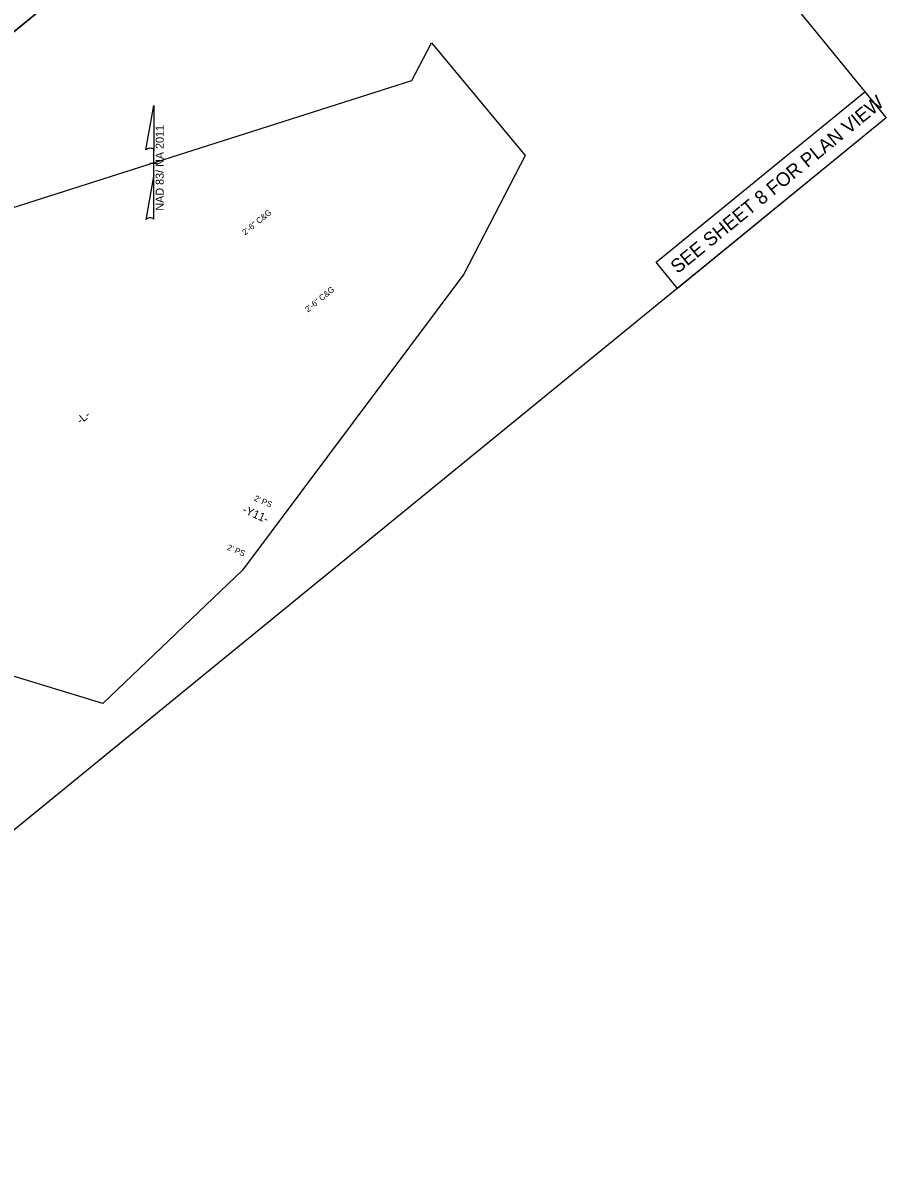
# Model space of a CAD drawing. Extents: x 1528967 to 2322919, y 597128 to 795043.
# Drawn here: x 2322186 to 2322919, y 597128 to 598094 of the extents above; entities that cross this region are included whole.
import ezdxf

# ---------------------------------------------------------------- set-up
doc = ezdxf.new("R2010")
doc.units = 0
for name, color, linetype in [('Default', 7, 'Continuous'), ('Prop Dimension Text', 7, 'Continuous'), ('Prop Horizontal Alignment Station Label', 7, 'Continuous'), ('Prop North Arrow NAD83 for Plan Sheets CELL', 7, 'Continuous'), ('Scratch_Level_1', 7, 'Continuous'), ('Sheet Plan CELL', 7, 'Continuous')]:
    doc.layers.add(name, color=color, linetype=linetype)

msp = doc.modelspace()

# ---------------------------------------------------------------- linework, layer by layer
at = {"layer": 'Default'}
msp.add_lwpolyline([(2322723.55, 597890.52), (2322900.73, 598035.15), (2322918.85, 598012.95), (2322741.67, 597868.32)], close=True, dxfattribs=at)
at = {"layer": 'Prop North Arrow NAD83 for Plan Sheets CELL'}
for p, q in [((2322290.71, 597985.8), (2322297.3, 598023.65)), ((2322297.34, 598023.65), (2322297.3, 598023.65)), ((2322297.34, 598023.65), (2322297.3, 598023.65)), ((2322297.34, 598023.65), (2322297.34, 597985.09)), ((2322297.34, 597965.08), (2322297.34, 597986.22)), ((2322297.34, 597985.09), (2322297.34, 597986.18)), ((2322294.16, 597974.22), (2322300.59, 597974.66)), ((2322297.34, 597965.08), (2322290.63, 597926.5)), ((2322294.12, 597974.22), (2322294.08, 597974.22)), ((2322296.98, 597974.41), (2322294.12, 597974.22)), ((2322297.38, 597927.13), (2322297.34, 597965.08))]:
    msp.add_line(p, q, dxfattribs=at)
for centre, start_param, end_param in [((2322294.03, 597985.63), 0.176011, 2.867842), ((2322294.03, 597926.6), 0.160951, 3.101216)]:
    msp.add_ellipse(centre, major_axis=(3.4, 0.27), ratio=0.460709, start_param=start_param, end_param=end_param, dxfattribs=at)
at = {"layer": 'Scratch_Level_1'}
msp.add_lwpolyline([(2321910.68, 597777.51), (2322002.13, 597862.19), (2322049.11, 597896), (2322516.32, 598044.87), (2322532.88, 598076.76), (2322612.46, 597981.15), (2322560.58, 597880.33), (2322421.38, 597694.16), (2322372.52, 597629.14), (2322254, 597516.08), (2322170.58, 597541.65), (2322016.23, 597501.11), (2321872.65, 597676.99)], close=True, dxfattribs=at)
at = {"layer": 'Sheet Plan CELL'}
for points in [[(2321170.32, 597940.94), (2321932.56, 598563.23), (2321956.07, 598534.43), (2322069.68, 598627.18), (2322128.74, 598554.85), (2322190.77, 598605.49), (2322241.95, 598542.8), (2322388.56, 598662.49), (2322586.87, 598419.63), (2321502.31, 597534.26)], [(2321502.31, 597534.26), (2322586.86, 598419.62), (2322918.85, 598012.95), (2321834.3, 597127.59)]]:
    msp.add_lwpolyline(points, close=True, dxfattribs=at)

# ---------------------------------------------------------------- texts
at = {"layer": 'Default'}
msp.add_text('SEE SHEET 8 FOR PLAN VIEW', height=11.6664, rotation=39.22607, dxfattribs=at).set_placement((2322741.85, 597880.36))
at = {"layer": 'Prop Dimension Text'}
for s, rotation, p in [('2\'-6" C&G', 39.22799, (2322374.85, 597913.15)), ('2\'-6" C&G', 39.22799, (2322428.19, 597847.8)), ("2' PS", 337.48383, (2322381.97, 597688.36)), ("2' PS", 337.48383, (2322359.11, 597646.7))]:
    msp.add_text(s, height=5, rotation=rotation, dxfattribs=at).set_placement(p)
at = {"layer": 'Prop Horizontal Alignment Station Label'}
for s, rotation, p in [('-L-', 39.22799, (2322235.28, 597752.68)), ('-Y11-', 336.2198, (2322371.91, 597678.18))]:
    msp.add_text(s, height=7, rotation=rotation, dxfattribs=at).set_placement(p)
at = {"layer": 'Prop North Arrow NAD83 for Plan Sheets CELL'}
msp.add_text('NAD 83/ NA 2011', height=6.845, rotation=90, dxfattribs=at).set_placement((2322305.79, 597934.28))

doc.saveas('drawing.dxf')
